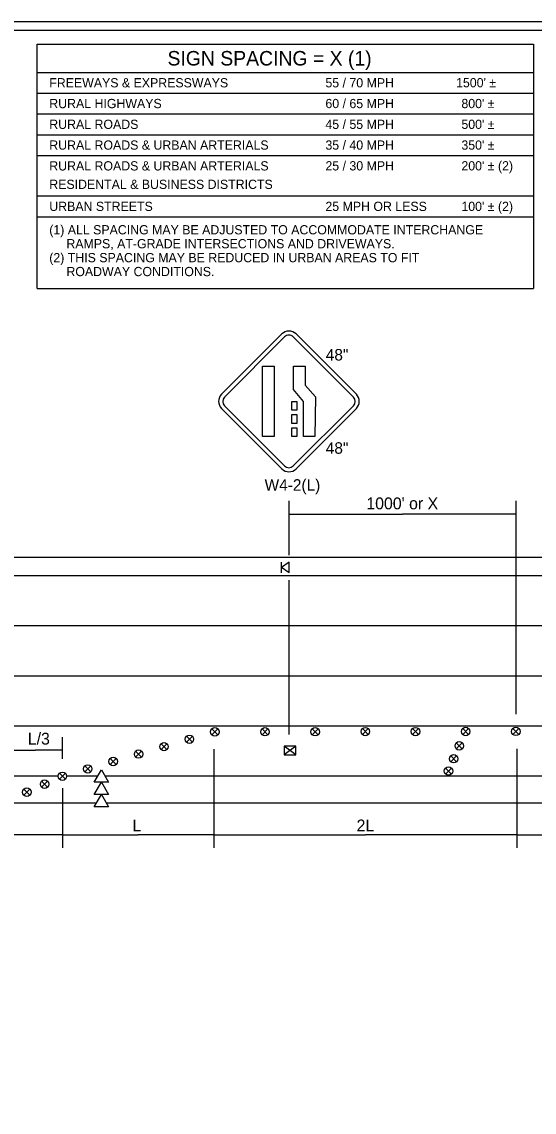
# Model space of a CAD drawing. Extents: x 99988 to 100172, y 99995 to 100047.
# Drawn here: x 100004.79 to 100008.68, y 100002.17 to 100010.44 of the extents above; entities that cross this region are included whole.
import ezdxf

# ---------------------------------------------------------------- set-up
doc = ezdxf.new("R2010")
doc.units = 0
for name, color, linetype in [('Default', 7, 'Continuous'), ('Level 15', 7, 'Continuous'), ('Level 20', 7, 'Continuous'), ('SH_GI_PlotLimits', 7, 'Continuous'), ('SH_GI_SheetBorder', 7, 'Continuous'), ('SH_TI_SignSpacing35to70Note', 7, 'Continuous'), ('TR_SN_WarningSigns', 7, 'Continuous'), ('TR_WZ_SequentialArrowTypeC', 7, 'Continuous'), ('TR_WZ_WorkZoneDetails', 7, 'Continuous')]:
    doc.layers.add(name, color=color, linetype=linetype)

msp = doc.modelspace()

# ---------------------------------------------------------------- linework, layer by layer
at = {"layer": 'Default'}
for p, q in [((100006.8147, 100006.3399), (100006.7569, 100006.2996)), ((100006.7569, 100006.2594), (100006.7569, 100006.3399)), ((100006.8147, 100006.2594), (100006.8147, 100006.3399)), ((100006.8147, 100006.2594), (100006.7569, 100006.2996)), ((100002.5342, 100005.8585), (100011.4419, 100005.8585)), ((100002.5316, 100005.4785), (100014.1914, 100005.4785)), ((100002.5342, 100005.0998), (100011.6853, 100005.0998)), ((100006.2742, 100005.076), (100006.2289, 100005.0307)), ((100006.2289, 100005.076), (100006.2742, 100005.0307)), ((100006.6549, 100005.0765), (100006.6097, 100005.0313)), ((100006.6097, 100005.0765), (100006.6549, 100005.0313)), ((100007.0357, 100005.077), (100006.9904, 100005.0318)), ((100006.9904, 100005.077), (100007.0357, 100005.0318)), ((100007.4165, 100005.0776), (100007.3712, 100005.0323)), ((100007.3712, 100005.0776), (100007.4165, 100005.0323)), ((100007.7972, 100005.0781), (100007.752, 100005.0329)), ((100007.752, 100005.0781), (100007.7972, 100005.0329)), ((100008.178, 100005.0787), (100008.1327, 100005.0334)), ((100008.1327, 100005.0787), (100008.178, 100005.0334)), ((100008.5587, 100005.0792), (100008.5135, 100005.034)), ((100008.5135, 100005.0792), (100008.5587, 100005.034)), ((100008.5587, 100005.0792), (100008.5135, 100005.034)), ((100008.5135, 100005.0792), (100008.5587, 100005.034)), ((100006.0814, 100005.0198), (100006.0361, 100004.9745)), ((100006.0361, 100005.0198), (100006.0814, 100004.9745)), ((100005.6958, 100004.9074), (100005.6505, 100004.8621)), ((100005.6505, 100004.9074), (100005.6958, 100004.8621)), ((100005.8886, 100004.9636), (100005.8433, 100004.9183)), ((100005.8433, 100004.9636), (100005.8886, 100004.9183)), ((100006.8652, 100004.88), (100006.7781, 100004.9452)), ((100006.8652, 100004.9452), (100006.7781, 100004.88)), ((100006.8217, 100004.9126), (100006.8217, 100004.9126)), ((100006.8218, 100004.9125), (100006.8218, 100004.9125)), ((100008.129, 100004.97), (100008.0837, 100004.9248)), ((100008.0837, 100004.97), (100008.129, 100004.9248)), ((100005.503, 100004.8512), (100005.4577, 100004.8059)), ((100005.4577, 100004.8512), (100005.503, 100004.8059)), ((100008.0867, 100004.8721), (100008.0415, 100004.8268)), ((100008.0415, 100004.8721), (100008.0867, 100004.8268)), ((100005.1173, 100004.7388), (100005.0721, 100004.6935)), ((100005.0721, 100004.7388), (100005.1173, 100004.6935)), ((100005.3102, 100004.795), (100005.2649, 100004.7497)), ((100005.2649, 100004.795), (100005.3102, 100004.7497)), ((100008.0474, 100004.7789), (100008.0021, 100004.7336)), ((100008.0021, 100004.7789), (100008.0474, 100004.7336)), ((100004.9825, 100004.6788), (100004.9373, 100004.6336)), ((100004.9373, 100004.6788), (100004.9825, 100004.6336)), ((100004.8477, 100004.6189), (100004.8025, 100004.5736)), ((100004.8025, 100004.6189), (100004.8477, 100004.5736))]:
    msp.add_line(p, q, dxfattribs=at)
msp.add_lwpolyline([(100006.8652, 100004.88), (100006.8652, 100004.9452), (100006.7781, 100004.9452), (100006.7781, 100004.88)], close=True, dxfattribs=at)
for centre in [(100006.2516, 100005.0533), (100006.6323, 100005.0539), (100007.0131, 100005.0544), (100007.3938, 100005.055), (100007.7746, 100005.0555), (100008.1553, 100005.056), (100008.5361, 100005.0566), (100008.5361, 100005.0566), (100006.0588, 100004.9971), (100005.6731, 100004.8848), (100005.8659, 100004.941), (100008.1064, 100004.9474), (100005.4803, 100004.8286), (100008.0641, 100004.8494), (100005.0947, 100004.7162), (100005.2875, 100004.7724), (100008.0247, 100004.7563), (100004.9599, 100004.6562), (100004.8251, 100004.5963)]:
    msp.add_circle(centre, 0.032, dxfattribs=at)
at = {"layer": 'Level 15'}
for p, q in [((100006.8142, 100006.7045), (100007.6747, 100006.7045)), ((100008.5352, 100006.7045), (100007.6747, 100006.7045)), ((100004.6854, 100004.9138), (100004.8899, 100004.9138)), ((100005.0944, 100004.9138), (100004.8899, 100004.9138)), ((100005.0944, 100004.2732), (100004.6704, 100004.2732)), ((100005.0944, 100004.2732), (100005.6694, 100004.2732)), ((100006.2444, 100004.2732), (100005.6694, 100004.2732)), ((100006.2444, 100004.2732), (100007.3944, 100004.2732)), ((100008.5444, 100004.2732), (100007.3944, 100004.2732)), ((100008.5444, 100004.2732), (100009.1194, 100004.2732))]:
    msp.add_line(p, q, dxfattribs=at)
at = {"layer": 'SH_GI_PlotLimits'}
msp.add_lwpolyline([(99999.3125, 99999.9375), (100015.8125, 99999.9375), (100015.8125, 100010.4375), (99999.3125, 100010.4375)], close=True, dxfattribs=at)
at = {"layer": 'SH_GI_SheetBorder'}
msp.add_line((100000, 100010.375), (100015.75, 100010.375), dxfattribs=at)
at = {"layer": 'SH_TI_SignSpacing35to70Note'}
for p, q in [((100004.9044, 100010.0539), (100008.6699, 100010.0539)), ((100004.9044, 100009.8965), (100008.6699, 100009.8965)), ((100004.9044, 100009.739), (100008.6699, 100009.739)), ((100004.9044, 100009.5816), (100008.6699, 100009.5816)), ((100004.9044, 100009.4242), (100008.6699, 100009.4242)), ((100004.9044, 100009.1168), (100008.6699, 100009.1168)), ((100004.9044, 100008.9594), (100008.6699, 100008.9594)), ((100004.9044, 100008.4158), (100008.6699, 100008.4158))]:
    msp.add_line(p, q, dxfattribs=at)
msp.add_lwpolyline([(100004.9044, 100008.4158), (100004.9044, 100010.2684), (100008.6699, 100010.2684), (100008.6699, 100008.4158)], dxfattribs=at)
at = {"layer": 'TR_SN_WarningSigns'}
for p, q in [((100006.3029, 100007.6134), (100006.7599, 100008.0703)), ((100006.3247, 100007.5917), (100006.7816, 100008.0486)), ((100006.8469, 100008.0486), (100007.3038, 100007.5917)), ((100006.8687, 100008.0703), (100007.3256, 100007.6134)), ((100006.7599, 100007.0478), (100006.3029, 100007.5047)), ((100006.7816, 100007.0695), (100006.3247, 100007.5264)), ((100007.3038, 100007.5264), (100006.8469, 100007.0695)), ((100007.3256, 100007.5047), (100006.8687, 100007.0478))]:
    msp.add_line(p, q, dxfattribs=at)
for points in [[(100006.7028, 100007.2924), (100006.6132, 100007.2924), (100006.6132, 100007.8257), (100006.7028, 100007.8257)], [(100006.9374, 100007.8257), (100006.9374, 100007.6819), (100007.0153, 100007.5927), (100007.0114, 100007.2924), (100006.9257, 100007.2924), (100006.9257, 100007.5591), (100006.8479, 100007.6483), (100006.8479, 100007.8257)], [(100006.8746, 100007.4924), (100006.8351, 100007.4924), (100006.8351, 100007.5591), (100006.8746, 100007.5591)], [(100006.8746, 100007.3924), (100006.8351, 100007.3924), (100006.8351, 100007.4591), (100006.8746, 100007.4591)], [(100006.8746, 100007.2924), (100006.8351, 100007.2924), (100006.8351, 100007.3591), (100006.8746, 100007.3591)]]:
    msp.add_lwpolyline(points, close=True, dxfattribs=at)
for centre, radius, start, end in [((100006.8143, 100008.0159), 0.0769, 44.99627, 134.99965), ((100006.8143, 100008.0159), 0.0462, 44.99627, 134.99965), ((100006.3574, 100007.5591), 0.0769, 134.99657, 224.99357), ((100006.3574, 100007.5591), 0.0462, 134.99657, 224.99357), ((100007.2712, 100007.559), 0.0462, 314.99936, 44.99485), ((100007.2712, 100007.559), 0.0769, 314.99936, 44.99485), ((100006.8142, 100007.1022), 0.0462, 225, 314.99958), ((100006.8142, 100007.1022), 0.0769, 225, 314.99958)]:
    msp.add_arc(centre, radius, start, end, dxfattribs=at)
at = {"layer": 'TR_WZ_SequentialArrowTypeC'}
msp.add_lwpolyline([(100005.4445, 100004.4855), (100005.3365, 100004.4855), (100005.3905, 100004.5788), (100005.3365, 100004.5788), (100005.3905, 100004.6721), (100005.3365, 100004.6721), (100005.3905, 100004.7654), (100005.4445, 100004.6721), (100005.3905, 100004.6721), (100005.4445, 100004.5788), (100005.3905, 100004.5788)], close=True, dxfattribs=at)
at = {"layer": 'TR_WZ_WorkZoneDetails'}
for p, q in [((100006.8142, 100006.8045), (100006.8142, 100006.3928)), ((100008.5352, 100006.8045), (100008.5352, 100005.1886)), ((100002.5342, 100006.3767), (100014.2093, 100006.3767)), ((100002.5342, 100006.2379), (100009.125, 100006.2379)), ((100006.8142, 100006.2024), (100006.8142, 100005.0343)), ((100005.0944, 100004.8482), (100005.0944, 100005.0138)), ((100006.2444, 100004.9213), (100006.2444, 100004.1732)), ((100008.5444, 100004.9246), (100008.5444, 100004.1732)), ((100002.5342, 100004.7201), (100005.0601, 100004.7201)), ((100005.1267, 100004.7201), (100005.3622, 100004.7201)), ((100005.4188, 100004.7201), (100006.9431, 100004.7201)), ((100006.9431, 100004.7201), (100009.1923, 100004.7201)), ((100005.0944, 100004.6265), (100005.0944, 100004.1732)), ((100004.7166, 100004.5142), (100005.3535, 100004.5142)), ((100005.4304, 100004.5142), (100009.1205, 100004.5142))]:
    msp.add_line(p, q, dxfattribs=at)

# ---------------------------------------------------------------- texts
at = {"layer": 'Level 20'}
msp.add_text("1000' or X", height=0.09, rotation=360, dxfattribs=at).set_placement((100007.4016, 100006.7407))
for s, p in [('L/3', (100004.8323, 100004.9565)), ('L', (100005.6261, 100004.2982)), ('2L', (100007.3274, 100004.2982))]:
    msp.add_text(s, height=0.09, dxfattribs=at).set_placement(p)
at = {"layer": 'SH_TI_SignSpacing35to70Note'}
for s, height, p in [('SIGN SPACING = X (1)', 0.11, (100005.8925, 100010.1061)), ('FREEWAYS & EXPRESSWAYS', 0.07, (100004.9954, 100009.9402)), ('55 / 70 MPH', 0.07, (100007.091, 100009.9402)), ("1500' ±", 0.07, (100008.0826, 100009.9409)), ('RURAL HIGHWAYS', 0.07, (100004.9954, 100009.7828)), ('60 / 65 MPH', 0.07, (100007.091, 100009.7828)), ("800' ±", 0.07, (100008.123, 100009.7828)), ('RURAL ROADS', 0.07, (100004.9954, 100009.6253)), ('45 / 55 MPH', 0.07, (100007.091, 100009.6253)), ("500' ±", 0.07, (100008.123, 100009.6253)), ('RURAL ROADS & URBAN ARTERIALS', 0.07, (100004.9954, 100009.4679)), ('35 / 40 MPH', 0.07, (100007.091, 100009.4679)), ("350' ± ", 0.07, (100008.123, 100009.4679)), ('RURAL ROADS & URBAN ARTERIALS', 0.07, (100004.9954, 100009.3102)), ('25 / 30 MPH', 0.07, (100007.091, 100009.3105)), ("200' ± (2)", 0.07, (100008.123, 100009.3105)), ('RESIDENTAL & BUSINESS DISTRICTS', 0.07, (100004.9954, 100009.1702)), ('URBAN STREETS', 0.07, (100004.9954, 100009.0031)), ('25 MPH OR LESS', 0.07, (100007.091, 100009.0031)), ("100' ± (2) ", 0.07, (100008.123, 100009.0031)), ('(1) ALL SPACING MAY BE ADJUSTED TO ACCOMMODATE INTERCHANGE ', 0.07, (100004.9953, 100008.8255)), ('     RAMPS, AT-GRADE INTERSECTIONS AND DRIVEWAYS.', 0.07, (100004.9953, 100008.7199)), ('(2) THIS SPACING MAY BE REDUCED IN URBAN AREAS TO FIT  ', 0.07, (100004.9953, 100008.6143)), ('     ROADWAY CONDITIONS.', 0.07, (100004.9953, 100008.5088))]:
    msp.add_text(s, height=height, dxfattribs=at).set_placement(p)
at = {"layer": 'TR_SN_WarningSigns'}
for s, p in [('48"', (100007.0938, 100007.8689)), ('48"', (100007.0938, 100007.1618)), ('W4-2(L)', (100006.6294, 100006.8815))]:
    msp.add_text(s, height=0.0875, rotation=360, dxfattribs=at).set_placement(p)

doc.saveas('drawing.dxf')
